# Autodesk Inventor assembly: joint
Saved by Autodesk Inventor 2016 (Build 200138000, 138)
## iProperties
Created: 2013-10
Part Number: joint
Material: Générique
Document SubType Name: Assembly
Designer: Bruno
Author: Bruno
Sending System: SolidWorks 2013
Last Author: christophe
Last Saved: 2014-02-15
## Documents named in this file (3)
- D:\Cours\Systèmes\SI\Robot Haptique\Documentations_pedagogique\Modèle solidworks\Réel\joint.iam
- D:\Cours\Systèmes\SI\Robot Haptique\Documentations_pedagogique\Modèle solidworks\Réel\joint.ipt
- D:\Cours\Systèmes\SI\Robot Haptique\Documentations_pedagogique\Modèle solidworks\Réel\AXE BRAS.ipt
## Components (2 placed, 2 different names)
1. joint:1
2. AXE BRAS:1
